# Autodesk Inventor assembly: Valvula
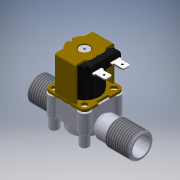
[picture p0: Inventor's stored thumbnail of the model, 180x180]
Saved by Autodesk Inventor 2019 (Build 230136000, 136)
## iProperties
Created: 2019-04
Part Number: Valvula
Document SubType Name: Assembly
Designer: Plo
Author: Plo
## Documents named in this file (6)
- C:\Users\HP UltraBook\3D Objects\Valve\Valvula.iam
- C:\Users\HP UltraBook\3D Objects\Valve\Valve.ipt
- C:\Users\HP UltraBook\3D Objects\Valve\Actuador.ipt
- C:\Users\HP UltraBook\3D Objects\Valve\Base1.ipt
- C:\Users\HP UltraBook\3D Objects\Valve\Solenoide.ipt
- C:\Users\HP UltraBook\3D Objects\Valve\Base2.ipt
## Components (5 placed, 5 different names)
1. Valve:1 — Insert:1, Angle:1
2. Actuador:1 — Insert:1, Insert:2
3. Base1:1 — Insert:2, Insert:3, Mate:1, Mate:2, Mate:3
4. Solenoide:1 — Insert:3
5. Base2:1 — Mate:1, Mate:2, Mate:3, Mate:4
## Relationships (8: Mate 4, Insert 3, Angle 1)
- Insert:1: Valve:1 ↔ Actuador:1
- Insert:2: Actuador:1 ↔ Base1:1
- Insert:3: Base1:1 ↔ Solenoide:1
- Mate:1: Base1:1 ↔ Base2:1
- Mate:2: Base1:1 ↔ Base2:1
- Mate:3: Base1:1 ↔ Base2:1
- Mate:4: Base2:1
- Angle:1: Valve:1
